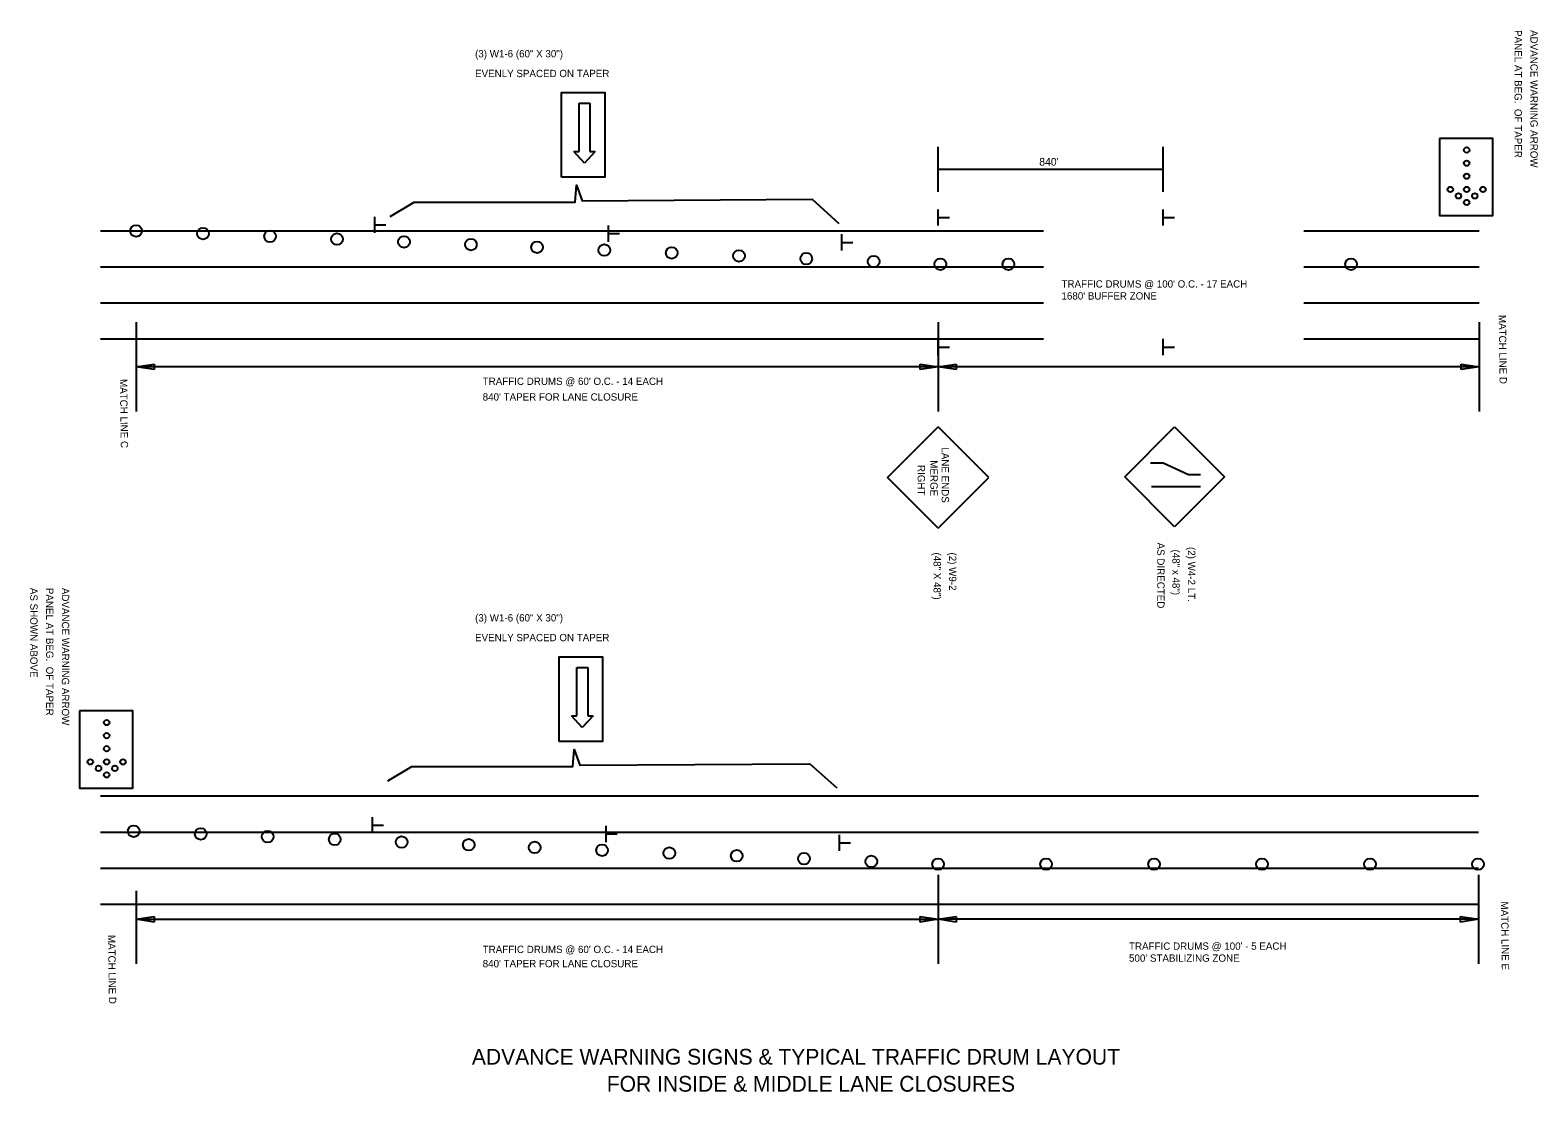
# Model space of a CAD drawing. Extents: x -100 to 745, y -1581 to -107.
# Drawn here: x -83.2 to 45, y -690.9 to -600.6 of the extents above; entities that cross this region are included whole.
import ezdxf

# ---------------------------------------------------------------- set-up
doc = ezdxf.new("R2010")
doc.units = 0
doc.layers.add('Default', color=7, linetype='Continuous')

msp = doc.modelspace()

# ---------------------------------------------------------------- linework, layer by layer
at = {"layer": 'Default'}
for p, q in [((-36.55, -610.93), (-36.55, -606.82)), ((-36.55, -606.82), (-35.64, -606.82)), ((-35.64, -606.82), (-35.64, -610.93)), ((-36.09, -611.93), (-37.01, -610.93)), ((-37.01, -610.93), (-36.55, -610.93)), ((-35.18, -610.93), (-36.09, -611.93)), ((-35.64, -610.93), (-35.18, -610.93)), ((-6.03, -614.35), (-6.03, -610.52)), ((13.11, -614.35), (13.11, -610.52)), ((-6.03, -612.43), (13.11, -612.43)), ((-53.95, -616.47), (-53.95, -617.85)), ((-6.03, -617.22), (-6.03, -615.85)), ((-6.01, -616.54), (-5.07, -616.54)), ((13.11, -617.22), (13.11, -615.85)), ((13.13, -616.54), (14.07, -616.54)), ((-77.24, -617.68), (2.93, -617.68)), ((-53.93, -617.16), (-52.99, -617.16)), ((-34.09, -617.22), (-34.09, -618.6)), ((25.06, -617.68), (39.98, -617.68)), ((-34.07, -617.91), (-33.13, -617.91)), ((-14.24, -617.97), (-14.24, -619.35)), ((-14.22, -618.66), (-13.28, -618.66)), ((-77.24, -620.74), (2.93, -620.74)), ((25.06, -620.74), (39.98, -620.74)), ((-77.24, -623.8), (2.93, -623.8)), ((25.06, -623.8), (39.98, -623.8)), ((-74.22, -625.45), (-74.22, -633.03)), ((-6.03, -625.45), (-6.03, -633.03)), ((39.98, -625.45), (39.98, -633.03)), ((-74.22, -626.83), (-74.22, -633.03)), ((-77.24, -626.87), (2.93, -626.87)), ((-6.03, -628.26), (-6.03, -626.88)), ((-6.01, -627.57), (-5.07, -627.57)), ((13.11, -628.25), (13.11, -626.87)), ((13.13, -627.56), (14.07, -627.56)), ((25.06, -626.87), (39.98, -626.87)), ((-74.22, -629.24), (-72.69, -629.01)), ((-6.03, -629.24), (-74.22, -629.24)), ((-72.69, -629.47), (-74.22, -629.24)), ((-72.69, -629.01), (-72.69, -629.47)), ((-7.56, -629.47), (-7.56, -629.01)), ((-7.56, -629.01), (-6.03, -629.24)), ((-6.03, -629.24), (-7.56, -629.47)), ((-6.03, -629.24), (-4.5, -629.01)), ((-4.5, -629.47), (-6.03, -629.24)), ((25.06, -629.24), (-6.03, -629.24)), ((-4.5, -629.01), (-4.5, -629.47)), ((39.98, -629.24), (25.06, -629.24)), ((38.45, -629.47), (38.45, -629.01)), ((38.45, -629.01), (39.98, -629.24)), ((39.98, -629.24), (38.45, -629.47)), ((-10.33, -638.66), (-6.02, -634.35)), ((-1.71, -638.66), (-6.02, -634.35)), ((9.84, -638.59), (14.08, -634.35)), ((14.08, -634.35), (18.33, -638.59)), ((13.11, -637.43), (12.03, -637.43)), ((15.27, -638.42), (13.11, -637.43)), ((-6.02, -642.96), (-10.33, -638.66)), ((-6.02, -642.96), (-1.71, -638.66)), ((14.08, -642.84), (9.84, -638.59)), ((12.12, -639.41), (16.29, -639.41)), ((18.33, -638.59), (14.08, -642.84)), ((16.29, -638.42), (15.27, -638.42)), ((-36.74, -658.93), (-36.74, -654.82)), ((-36.74, -654.82), (-35.82, -654.82)), ((-35.82, -654.82), (-35.82, -658.93)), ((-36.28, -659.93), (-37.19, -658.93)), ((-37.19, -658.93), (-36.74, -658.93)), ((-35.36, -658.93), (-36.28, -659.93)), ((-35.82, -658.93), (-35.36, -658.93)), ((-77.24, -665.74), (39.92, -665.74)), ((-54.14, -667.53), (-54.14, -668.91)), ((-77.24, -668.81), (39.92, -668.81)), ((-54.12, -668.22), (-53.18, -668.22)), ((-34.29, -668.29), (-34.29, -669.66)), ((-34.27, -668.97), (-33.33, -668.97)), ((-14.43, -669.04), (-14.43, -670.42)), ((-14.41, -669.72), (-13.47, -669.72)), ((-77.24, -671.87), (39.92, -671.87)), ((-6.03, -672.44), (-6.03, -680.02)), ((39.92, -672.44), (39.92, -680.02)), ((-74.22, -673.82), (-74.22, -680.02)), ((-77.24, -674.93), (39.92, -674.93)), ((-74.22, -676.23), (-72.69, -676)), ((-72.69, -676.46), (-74.22, -676.23)), ((-74.22, -676.23), (-6.03, -676.23)), ((-72.69, -676), (-72.69, -676.46)), ((-7.56, -676.46), (-7.56, -676)), ((-7.56, -676), (-6.03, -676.23)), ((-6.03, -676.23), (-7.56, -676.46)), ((-6.03, -676.23), (-4.5, -676)), ((39.92, -676.23), (-6.03, -676.23)), ((-4.5, -676.46), (-6.03, -676.23)), ((-4.5, -676), (-4.5, -676.46)), ((38.39, -676.46), (38.39, -676)), ((38.39, -676), (39.92, -676.23)), ((39.92, -676.23), (38.39, -676.46))]:
    msp.add_line(p, q, dxfattribs=at)
for points in [[(-38.05, -613.1), (-38.05, -605.9), (-34.37, -605.9), (-34.37, -613.1)], [(36.59, -609.82), (36.59, -616.38), (41.13, -616.38), (41.13, -609.82)], [(-38.24, -661.1), (-38.24, -653.9), (-34.56, -653.9), (-34.56, -661.1)], [(-79.04, -658.51), (-79.04, -665.07), (-74.5, -665.07), (-74.5, -658.51)]]:
    msp.add_lwpolyline(points, close=True, dxfattribs=at)
for points in [[(-52.62, -616.44), (-50.58, -615.23), (-36.9, -615.23), (-36.78, -613.79), (-36.3, -615.11), (-16.75, -614.99), (-14.47, -617.04)], [(-52.81, -664.44), (-50.77, -663.24), (-37.09, -663.24), (-36.97, -661.79), (-36.49, -663.12), (-16.93, -663), (-14.65, -665.04)]]:
    msp.add_lwpolyline(points, dxfattribs=at)
for centre, radius in [((38.91, -610.8), 0.231), ((38.91, -611.92), 0.231), ((37.52, -614.15), 0.231), ((38.91, -613.03), 0.231), ((38.91, -614.15), 0.231), ((40.3, -614.15), 0.231), ((38.21, -614.7), 0.231), ((38.91, -615.26), 0.231), ((39.6, -614.7), 0.231), ((-74.22, -617.68), 0.495), ((-68.53, -617.91), 0.495), ((-62.83, -618.14), 0.495), ((-57.14, -618.38), 0.495), ((-51.44, -618.61), 0.495), ((-45.75, -618.84), 0.495), ((-40.13, -619.07), 0.495), ((-34.41, -619.31), 0.495), ((-28.68, -619.55), 0.495), ((-22.96, -619.8), 0.495), ((-17.24, -620.04), 0.495), ((-11.51, -620.28), 0.495), ((-5.84, -620.51), 0.495), ((-0.05, -620.51), 0.495), ((29.08, -620.51), 0.495), ((-76.72, -659.5), 0.231), ((-76.72, -660.61), 0.231), ((-78.11, -662.84), 0.231), ((-76.72, -661.72), 0.231), ((-76.72, -662.84), 0.231), ((-75.33, -662.84), 0.231), ((-77.41, -663.39), 0.231), ((-76.72, -663.95), 0.231), ((-76.02, -663.39), 0.231), ((-74.42, -668.74), 0.495), ((-68.72, -668.97), 0.495), ((-63.03, -669.2), 0.495), ((-57.33, -669.43), 0.495), ((-51.64, -669.66), 0.495), ((-45.94, -669.89), 0.495), ((-40.33, -670.12), 0.495), ((-34.6, -670.36), 0.495), ((-28.88, -670.6), 0.495), ((-23.15, -670.83), 0.495), ((-17.43, -671.07), 0.495), ((-11.71, -671.31), 0.495), ((-6.03, -671.54), 0.495), ((3.15, -671.54), 0.495), ((12.33, -671.54), 0.495), ((21.51, -671.54), 0.495), ((30.69, -671.54), 0.495), ((39.87, -671.54), 0.495)]:
    msp.add_circle(centre, radius, dxfattribs=at)

# ---------------------------------------------------------------- texts
for s, height, rotation, p in [('PANEL AT BEG.  OF TAPER', 0.6222, 270, (42.98, -600.6)), ('ADVANCE WARNING ARROW', 0.6222, 270, (44.33, -600.6)), ('(3) W1-6 (60" X 30")', 0.6222, 0.0075, (-45.4, -602.92)), ('EVENLY SPACED ON TAPER', 0.6222, 0.0075, (-45.4, -604.6)), ('MATCH LINE D', 0.6222, 270.8059, (41.63, -624.83)), ('MATCH LINE C', 0.6222, 270.8059, (-75.6, -630.28)), ('LANE ENDS', 0.622, 270, (-5.73, -636.09)), ('RIGHT', 0.622, 270.2001, (-7.77, -637.59)), ('MERGE', 0.622, 270, (-6.69, -637.19)), ('AS DIRECTED ', 0.6222, 270, (12.6, -644.19)), ('(2) W4-2 LT.', 0.6222, 270, (15.21, -644.56)), ('(48" X 48")', 0.6222, 270, (-6.42, -645.03)), ('(2) W9-2', 0.622, 270, (-5.1, -645.03)), ('(48" x 48")', 0.6222, 270, (13.89, -644.78)), ('AS SHOWN ABOVE', 0.6222, 270, (-83.22, -648.04)), ('PANEL AT BEG.  OF TAPER', 0.6222, 270, (-81.87, -648.04)), ('ADVANCE WARNING ARROW', 0.6222, 270, (-80.53, -648.04)), ('(3) W1-6 (60" X 30")', 0.6222, 0.0075, (-45.4, -650.9)), ('EVENLY SPACED ON TAPER', 0.6222, 0.0075, (-45.4, -652.58)), ('MATCH LINE E', 0.6222, 270.8059, (41.82, -674.72)), ('MATCH LINE D', 0.6222, 270.8059, (-76.61, -677.56))]:
    msp.add_text(s, height=height, rotation=rotation, dxfattribs=at).set_placement(p)
for s, height, p in [("840'", 0.661, (2.57, -612.13)), ("TRAFFIC DRUMS @ 100' O.C. - 17 EACH", 0.6222, (4.46, -622.5)), ("1680' BUFFER ZONE", 0.6222, (4.46, -623.52)), ("TRAFFIC DRUMS @ 60' O.C. - 14 EACH", 0.6222, (-44.75, -630.78)), ("840' TAPER FOR LANE CLOSURE", 0.6222, (-44.75, -632.11)), ("TRAFFIC DRUMS @ 60' O.C. - 14 EACH", 0.6222, (-44.75, -679.1)), ("TRAFFIC DRUMS @ 100' - 5 EACH", 0.6222, (10.2, -678.82)), ("500' STABILIZING ZONE", 0.6222, (10.2, -679.84)), ("840' TAPER FOR LANE CLOSURE", 0.6222, (-44.75, -680.31)), ('ADVANCE WARNING SIGNS & TYPICAL TRAFFIC DRUM LAYOUT', 1.3387, (-45.67, -688.59)), ('FOR INSIDE & MIDDLE LANE CLOSURES', 1.3387, (-34.2, -690.89))]:
    msp.add_text(s, height=height, dxfattribs=at).set_placement(p)

doc.saveas('drawing.dxf')
